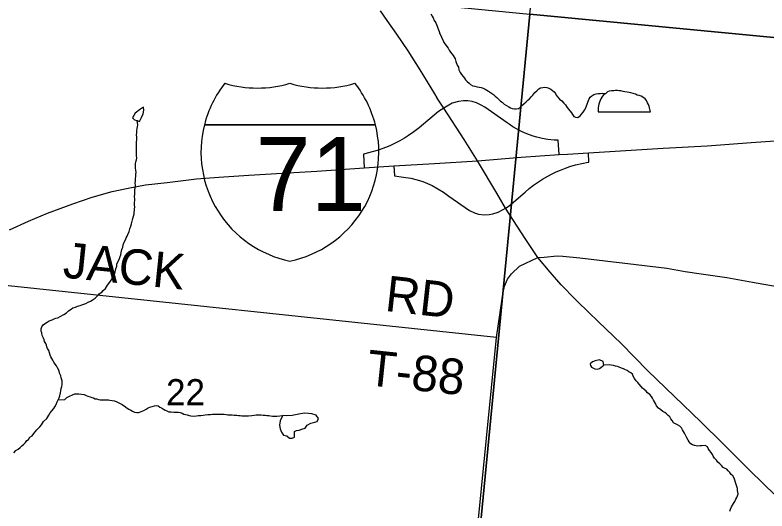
# Model space of a CAD drawing. Extents: x 1310247 to 1664935, y 284496 to 704931.
# Drawn here: x 1497662 to 1504004, y 515913 to 520097 of the extents above; entities that cross this region are included whole.
import ezdxf

# ---------------------------------------------------------------- set-up
doc = ezdxf.new("R2010")
doc.units = 0
for name, color, linetype in [('GM_X_Airport_Location_Class_3', 7, 'Continuous'), ('GM_X_County', 7, 'Continuous'), ('GM_X_County_Subdivision_Text', 7, 'Continuous'), ('GM_X_Interstate_Shield', 7, 'Continuous'), ('GM_X_Minor_River', 7, 'Continuous'), ('GM_X_Minor_River_Text', 7, 'Continuous'), ('GM_X_State_Shield', 7, 'Continuous'), ('GM_X_Township_Subdivision', 7, 'Continuous'), ('GM_X_US_Location', 7, 'Continuous'), ('GM_X_US_Route', 7, 'Continuous'), ('GM_X_US_Shield', 7, 'Continuous')]:
    doc.layers.add(name, color=color, linetype=linetype)

msp = doc.modelspace()

# ---------------------------------------------------------------- linework, layer by layer
at = {"layer": 'GM_X_County'}
for points in [[(1502528.3, 524873.1), (1507676.2, 524402.8), (1507180.6, 519609.2), (1502005.1, 520103.9)], [(1496845.7, 520606.4), (1502005.1, 520103.9), (1501457.6, 514459.3), (1496329.6, 514931.2)], [(1502005.1, 520103.9), (1507180.6, 519609.2), (1506637.6, 513990.6), (1501457.6, 514459.3)]]:
    msp.add_lwpolyline(points, close=True, dxfattribs=at)
at = {"layer": 'GM_X_County_Subdivision_Text'}
for points in [[(1501771.5, 517702.4), (1501779.6, 517756), (1501791.6, 517808.8), (1501816.5, 517868.7), (1501848.4, 517913.6), (1501916.8, 517977.7), (1502071.6, 518051)], [(1501722.1, 517377.3), (1497366.9, 517838.7), (1497333.5, 517849.9), (1497320.3, 517874.9), (1497324.8, 517900.7), (1497345.8, 517902.7), (1497363.7, 517887.9), (1497374.1, 517861.4), (1497366.9, 517839.7)], [(1501430.9, 514433.2), (1501430.9, 514433.2), (1501722.1, 517377.3), (1501771.5, 517702.4)]]:
    msp.add_lwpolyline(points, dxfattribs=at)
at = {"layer": 'GM_X_Interstate_Shield'}
for points in [[(1501222.1, 519397.5), (1501202.6, 519431.8), (1501077.9, 519634.3), (1500977.1, 519793.8), (1500882.9, 519935), (1500801.6, 520049.7), (1500744.8, 520131.6)], [(1502071.6, 518051), (1501963.7, 518212.3), (1501798.8, 518468), (1501724.8, 518592.9), (1501561.7, 518867.1), (1501451, 519047.2), (1501277.9, 519310.8), (1501223.5, 519394.9), (1501222.1, 519397.5)], [(1502071.6, 518051), (1502125.9, 518053.8), (1502234, 518064.2), (1502281.4, 518063.7), (1502425, 518049.8), (1502640.5, 518023.3), (1502901.8, 517991.4), (1503159.2, 517961.5), (1503314.2, 517933.9), (1503448.3, 517912.7), (1503664.5, 517881.6), (1503882.6, 517842.4), (1504090.6, 517805.5)], [(1502391.3, 517695.5), (1502389.8, 517697), (1502267.1, 517821.8), (1502174.6, 517927.5), (1502071.6, 518051)], [(1504087.5, 516035.1), (1504000.8, 516116.6), (1503830, 516283.1), (1503632, 516482.2), (1503445.9, 516664.2), (1503223.7, 516879.2), (1503000.5, 517096.1), (1502773.7, 517324.6), (1502583.1, 517507.6), (1502408.3, 517678.1), (1502391.3, 517695.5)]]:
    msp.add_lwpolyline(points, dxfattribs=at)
at = {"layer": 'GM_X_Minor_River'}
for points in [[(1503022.3, 519280.2), (1503013.4, 519312.6), (1503009.8, 519326.7), (1503004.2, 519340.9), (1502996.8, 519357.2), (1502987.3, 519375.5), (1502975.7, 519389.9), (1502958.1, 519402.5), (1502942.3, 519411), (1502926.4, 519417.5), (1502908.5, 519422), (1502894.6, 519428.5), (1502874.7, 519435.1), (1502856.8, 519439.6), (1502840.9, 519444.1), (1502824.9, 519446.6), (1502804.9, 519449.2), (1502790.9, 519451.7), (1502771, 519456.3), (1502757, 519458.7), (1502742.9, 519459.2), (1502726.9, 519459.7), (1502712.8, 519458.1), (1502692.7, 519458.7), (1502674.4, 519453.3), (1502660.2, 519447.7), (1502643.7, 519436.2), (1502625.2, 519422.7), (1502610.5, 519403.2), (1502604, 519389.3), (1502597.5, 519375.5), (1502591, 519361.7), (1502586.4, 519343.8), (1502583.9, 519329.8), (1502581.5, 519315.9), (1502580.9, 519297.9), (1502580.3, 519279.9)], [(1498653.6, 519229.4), (1498671.3, 519212.9), (1498693.2, 519206.3), (1498711.1, 519199.9), (1498728, 519231.6), (1498742.8, 519263.3), (1498749.6, 519293.3), (1498746.2, 519319.5), (1498711.5, 519296.2), (1498674.6, 519269)], [(1498674.6, 519269), (1498653.6, 519229.4)], [(1502580.3, 519279.9), (1503008.3, 519280.7), (1503022.3, 519280.2)], [(1499922.2, 516717.8), (1499907.5, 516692), (1499899.1, 516674.2), (1499894.1, 516636.2), (1499897.4, 516606), (1499910.8, 516577.5), (1499926.2, 516553.1), (1499954.2, 516546.4), (1499977.8, 516527.8), (1499999.9, 516527.2), (1500020.2, 516534.8), (1500018.9, 516562.9), (1500019.4, 516583), (1500035.7, 516592.6), (1500059.9, 516596), (1500080.2, 516603.6), (1500108.5, 516612.9), (1500127.2, 516636.5), (1500155.7, 516653.9), (1500192.1, 516663.1), (1500210.3, 516668.7), (1500221, 516694.5), (1500201.6, 516721.1), (1500165.7, 516732), (1500137.7, 516736.6), (1500099.6, 516739.6), (1500055.1, 516730.6)], [(1500055.1, 516730.6), (1500000.6, 516717.9), (1499954.3, 516717), (1499922.2, 516717.8)]]:
    msp.add_lwpolyline(points, dxfattribs=at)
at = {"layer": 'GM_X_Minor_River_Text'}
for points in [[(1501168.9, 520106.9), (1501180.3, 520086.5), (1501187.8, 520072.3), (1501197.1, 520049.9), (1501210.6, 520031.5), (1501216.2, 520017.3), (1501221.7, 520003.1), (1501229.2, 519986.8), (1501234.8, 519972.6), (1501238.3, 519958.5), (1501245.7, 519938.2), (1501255.1, 519917.9), (1501262.6, 519901.6), (1501274, 519881.3), (1501279.5, 519865.1), (1501291, 519850.7), (1501304.4, 519830.2), (1501314, 519815.9), (1501323.6, 519801.6), (1501335, 519783.2), (1501346.6, 519768.8), (1501356.2, 519754.5), (1501365.8, 519740.2), (1501373.3, 519725.9), (1501380.6, 519703.6), (1501391.7, 519673.2), (1501401.2, 519656.9), (1501406.5, 519634.7), (1501417.8, 519612.3), (1501427.2, 519594), (1501440.8, 519579.6), (1501454.4, 519565.1), (1501462, 519550.8), (1501475.6, 519536.4), (1501491.2, 519521.9), (1501504.9, 519511.5), (1501522.6, 519500.9), (1501540.6, 519496.3), (1501558.5, 519491.8), (1501576.5, 519489.2), (1501594.5, 519486.6), (1501610.4, 519480.1), (1501628.2, 519471.6), (1501641.9, 519463.1), (1501655.7, 519454.7), (1501681.3, 519437.9), (1501699, 519427.3), (1501710.6, 519412.9), (1501726.3, 519402.4), (1501739.9, 519386), (1501757.5, 519371.4), (1501771.2, 519361), (1501788.7, 519344.4), (1501808.5, 519333.8), (1501826.2, 519323.2), (1501842, 519314.7), (1501855.8, 519308.3), (1501873.8, 519305.7), (1501889.9, 519305.2), (1501908.1, 519308.6), (1501924.6, 519320.2), (1501937.1, 519333.8), (1501953.6, 519347.3)], [(1501953.6, 519347.3), (1501972.2, 519364.8), (1501986.8, 519378.3), (1502001.2, 519389.9), (1502015.9, 519407.5), (1502028.4, 519421.1), (1502047.2, 519442.6), (1502061.7, 519458.2), (1502080.3, 519473.6), (1502094.7, 519483.2), (1502112.9, 519486.7), (1502131, 519488.1), (1502147, 519485.6), (1502162.9, 519479.1), (1502180.7, 519470.5), (1502194.4, 519460.1), (1502208.1, 519449.7), (1502219.7, 519435.3), (1502227.3, 519421), (1502238.8, 519404.6), (1502254.3, 519386.1), (1502273.9, 519373.5), (1502291.3, 519352.9), (1502305, 519340.5), (1502314.5, 519324.1), (1502328, 519305.7), (1502345.4, 519285.1), (1502354.9, 519270.8), (1502362.5, 519256.5), (1502376.1, 519242.1), (1502389.9, 519235.7), (1502407.9, 519233.1), (1502428.5, 519246.5), (1502439, 519260.2), (1502453.6, 519277.8), (1502464.3, 519295.5), (1502475, 519315.2), (1502481.5, 519331), (1502488, 519344.8), (1502492.6, 519362.7), (1502499.1, 519376.5), (1502505.6, 519390.4), (1502512, 519404.2), (1502526.5, 519415.8), (1502544.9, 519425.2), (1502563.2, 519430.7), (1502581.4, 519434.1), (1502599.5, 519435.6), (1502615.6, 519437.1), (1502643.7, 519436.2)], [(1498672, 518547.1), (1498670.6, 518563.1), (1498671.4, 518587.1), (1498672, 518605.2), (1498672.6, 518623.2), (1498675, 518637.1), (1498677.8, 518661.1), (1498676.4, 518679.2), (1498679, 518697.1), (1498679.7, 518717.1), (1498680.3, 518735.1), (1498680.9, 518753.2), (1498683.4, 518769.1), (1498682, 518787.2), (1498678.6, 518805.3), (1498677.2, 518825.4), (1498679.7, 518841.4), (1498680.3, 518859.4), (1498686.9, 518875.2), (1498689.5, 518893.1), (1498688, 518909.2), (1498686.5, 518923.3), (1498687, 518939.3), (1498687.5, 518955.3), (1498688.1, 518971.3), (1498687, 518999.4), (1498687.8, 519023.4), (1498688.6, 519047.5), (1498689.2, 519067.5), (1498687.8, 519085.6), (1498688.4, 519103.6), (1498689, 519121.6), (1498691.6, 519139.5), (1498694.1, 519153.5), (1498696.7, 519171.4), (1498693.2, 519206.3)], [(1498040.5, 516885.5), (1498045.3, 516909.4), (1498047.8, 516925.4), (1498052.5, 516945.3), (1498057.1, 516963.2), (1498059.7, 516981.1), (1498060.2, 516995.1), (1498058.7, 517011.2), (1498051.6, 517037.5), (1498048.1, 517053.6), (1498038.8, 517075.9), (1498035.3, 517094.1), (1498020.1, 517120.6), (1498012.6, 517136.8), (1498001.1, 517151.2), (1497989.5, 517167.6), (1497982.1, 517185.9), (1497965, 517214.5), (1497959.4, 517228.6), (1497954, 517246.8), (1497946.6, 517267.1), (1497937.1, 517283.4), (1497931.5, 517297.6), (1497928, 517311.8), (1497922.4, 517326), (1497910.9, 517342.3), (1497907.4, 517356.5), (1497901.8, 517370.7), (1497892.5, 517393), (1497887.2, 517415.2), (1497881.6, 517429.4), (1497882.3, 517449.4), (1497888.9, 517467.2), (1497901.6, 517484.9), (1497934.4, 517505.9), (1497950.9, 517517.4), (1497975.3, 517526.7), (1497991.6, 517534.2), (1498005.9, 517539.8), (1498022, 517543.3), (1498042.5, 517554.7), (1498075.2, 517571.7), (1498095.8, 517585.1), (1498114.4, 517600.5), (1498135, 517615.9), (1498149.3, 517625.5), (1498173.7, 517632.8), (1498190, 517640.3), (1498210.3, 517647.7), (1498226.5, 517651.2), (1498242.9, 517658.7), (1498259.1, 517664.2), (1498279.5, 517673.6), (1498299.9, 517683), (1498314.3, 517692.5), (1498336.9, 517707.9), (1498359.8, 517731.2), (1498372.3, 517744.8), (1498394.9, 517760.2), (1498405.4, 517773.9), (1498424.1, 517791.3), (1498443, 517816.8), (1498461.9, 517842.3), (1498472.5, 517860), (1498483.2, 517879.7), (1498491.7, 517893.4), (1498502.4, 517911.1), (1498507, 517931), (1498513.9, 517956.9), (1498520.7, 517978.7), (1498521.2, 517994.7), (1498527.7, 518008.5), (1498536.4, 518028.3), (1498542.9, 518044.1), (1498549.5, 518060), (1498553.9, 518073.8), (1498558.6, 518093.7), (1498563.5, 518119.6), (1498572.2, 518139.4), (1498574.8, 518157.3), (1498583.6, 518181.1), (1498594.3, 518200.8), (1498600.9, 518216.6), (1498607.3, 518230.5), (1498613.8, 518244.3), (1498624.7, 518270), (1498631.5, 518293.8), (1498638.3, 518315.7), (1498645, 518335.5), (1498649.7, 518357.4), (1498656.5, 518381.2), (1498661.2, 518401.1), (1498665.8, 518419), (1498668.3, 518433), (1498670.7, 518446.9), (1498671.3, 518462.9), (1498671.7, 518476.9), (1498670.3, 518495), (1498671, 518515), (1498671.6, 518533), (1498672, 518547.1)], [(1502629.5, 517143.2), (1502622.2, 517175.5), (1502592.4, 517188.2), (1502556, 517179.1), (1502531.7, 517171.6), (1502513.2, 517154), (1502514.9, 517140), (1502524.6, 517125.7)], [(1503703, 516221.8), (1503691.5, 516238.1), (1503677.8, 516250.6), (1503664.2, 516265), (1503650.4, 516271.5), (1503634.6, 516280), (1503621, 516296.4), (1503605.4, 516310.9), (1503589.9, 516325.4), (1503578.3, 516341.8), (1503562.8, 516358.3), (1503551.4, 516376.7), (1503543.8, 516391), (1503532.3, 516407.4), (1503518.7, 516423.8), (1503509.3, 516440.1), (1503501.7, 516454.4), (1503483.9, 516465), (1503455.8, 516463.8), (1503437.6, 516462.4), (1503419.5, 516460.9), (1503405.5, 516461.4), (1503391.5, 516465.8), (1503375.7, 516472.3), (1503361.9, 516480.7), (1503348.3, 516495.2), (1503338.7, 516509.5), (1503327.4, 516529.9), (1503318, 516552.2), (1503308.6, 516570.5), (1503301, 516584.8), (1503291.5, 516599.1), (1503283.9, 516613.4), (1503268.4, 516629.9), (1503250.6, 516640.5), (1503232.8, 516649), (1503217, 516655.5), (1503203.6, 516676), (1503192, 516690.4), (1503184.5, 516706.6), (1503170.8, 516719.1), (1503157.3, 516733.5), (1503141.5, 516744), (1503125.7, 516752.5), (1503108.1, 516765.1), (1503088.5, 516781.7), (1503071.1, 516800.3), (1503063.6, 516818.5), (1503056.1, 516832.8), (1503046.5, 516847.1), (1503039, 516865.4), (1503031.5, 516879.6), (1503015.9, 516896.1), (1502996.3, 516910.8), (1502984.8, 516925.2), (1502969.1, 516937.7), (1502955.4, 516950.1), (1502943.9, 516964.5), (1502926.4, 516983.1), (1502914.8, 516997.5), (1502901.2, 517009.9), (1502887.8, 517030.3), (1502876.4, 517050.7), (1502868.9, 517067), (1502855.2, 517077.4), (1502839.4, 517087.9), (1502823.7, 517098.4), (1502809.9, 517104.9), (1502794, 517111.4), (1502776.1, 517117.9), (1502758.3, 517126.5), (1502744.4, 517130.9), (1502726.5, 517135.5), (1502708.5, 517140.1), (1502690.5, 517142.6), (1502676.6, 517145.1), (1502629.5, 517143.2)], [(1502524.6, 517125.7), (1502552.4, 517111), (1502572.4, 517108.5), (1502592.6, 517114), (1502629.5, 517143.2)], [(1498027.3, 516849.9), (1498081.7, 516854.2), (1498100.3, 516869.7), (1498120.7, 516881), (1498147.2, 516892.3), (1498165.6, 516901.7), (1498183.7, 516901.1), (1498199.8, 516902.7), (1498221.8, 516900), (1498245.8, 516895.2), (1498263.7, 516888.6), (1498277.5, 516882.2), (1498295.4, 516875.6), (1498309.3, 516871.2), (1498323.2, 516866.8), (1498337.1, 516860.3), (1498351, 516857.9), (1498367, 516853.4), (1498381, 516851), (1498395, 516850.5), (1498413.1, 516852), (1498433.2, 516851.4), (1498449.3, 516850.9), (1498463.3, 516848.4), (1498481.3, 516845.9), (1498501.2, 516841.2), (1498521.1, 516834.6), (1498544.8, 516821.9), (1498566.5, 516811.2), (1498594, 516792.3), (1498607.7, 516781.9), (1498621.5, 516771.4), (1498639.3, 516762.8), (1498653, 516754.4), (1498670.8, 516745.8), (1498690.9, 516743.2), (1498704.9, 516742.8), (1498719.2, 516748.4), (1498747.7, 516761.5), (1498768.2, 516772.9), (1498784.6, 516784.4), (1498798.8, 516788), (1498819.2, 516795.4), (1498837.4, 516800.8), (1498853.5, 516802.3), (1498869.5, 516799.8), (1498883.3, 516789.4), (1498897.1, 516782.9), (1498914.9, 516772.4), (1498928.6, 516763.9), (1498942.5, 516757.5), (1498960.4, 516750.9), (1498978.4, 516748.4), (1499000.4, 516747.7), (1499020.5, 516747.1), (1499040.6, 516746.5), (1499054.6, 516744), (1499072.4, 516737.5), (1499086.3, 516731), (1499114.2, 516724.1), (1499130, 516717.6), (1499146, 516715.1), (1499164, 516712.6), (1499192.3, 516715.7), (1499206.4, 516717.3), (1499230.5, 516718.5), (1499248.7, 516722), (1499264.9, 516723.5), (1499287.1, 516726.8), (1499311.2, 516728.1), (1499327.4, 516729.6), (1499355.5, 516730.7), (1499369.6, 516730.3), (1499385.6, 516729.8), (1499401.7, 516729.3), (1499425.8, 516728.5), (1499441.8, 516728), (1499457.8, 516725.5), (1499475.8, 516723), (1499494, 516724.4), (1499510, 516721.9), (1499532, 516721.3), (1499546, 516718.8), (1499560.1, 516718.4), (1499574.1, 516715.9), (1499592.1, 516715.4), (1499612.2, 516714.8), (1499632.3, 516716.1), (1499658.6, 516719.3), (1499678.8, 516722.7), (1499694.9, 516724.2), (1499708.9, 516723.8), (1499723, 516723.4), (1499739.1, 516722.9), (1499755.1, 516722.4), (1499771.2, 516721.9)], [(1497652.9, 516404.6), (1497669.6, 516422.1), (1497688.1, 516435.6), (1497706.6, 516449), (1497721.1, 516462.6), (1497735.7, 516478.2), (1497750.2, 516489.8), (1497760.8, 516507.5), (1497775.2, 516517.1), (1497787.8, 516534.7), (1497806.3, 516546.1), (1497821, 516567.7), (1497831.5, 516581.4), (1497846.1, 516597), (1497860.6, 516610.6), (1497871.1, 516624.3), (1497885.7, 516639.9), (1497902.8, 516669.4), (1497929.6, 516692.6), (1497938.1, 516706.4), (1497946.6, 516720.1), (1497957.3, 516739.8), (1497972, 516757.4), (1497988.7, 516776.9), (1497999.2, 516790.6), (1498009.9, 516810.3), (1498018.7, 516834.1), (1498027.3, 516849.9), (1498033.9, 516867.7), (1498040.5, 516885.5)], [(1499771.2, 516721.9), (1499785.2, 516719.5), (1499803.2, 516718.9), (1499817.2, 516716.5), (1499833.2, 516714), (1499853.3, 516713.3), (1499871.3, 516712.8), (1499922.2, 516717.8)], [(1503690.7, 515911.6), (1503697.3, 515927.4), (1503703.9, 515947.2), (1503712.5, 515963), (1503721, 515976.8), (1503731.6, 515994.5), (1503740.2, 516012.2), (1503750.7, 516026), (1503755.2, 516039.8), (1503759.8, 516057.7), (1503756.7, 516085.9), (1503755.3, 516102), (1503749.8, 516120.1), (1503744.3, 516136.3), (1503738.9, 516154.5), (1503733.5, 516172.7), (1503726.1, 516191), (1503716.6, 516209.3), (1503703, 516221.8)]]:
    msp.add_lwpolyline(points, dxfattribs=at)
at = {"layer": 'GM_X_State_Shield'}
msp.add_lwpolyline([(1497615.7, 518285.1), (1497776.1, 518357.6), (1497936.4, 518426.1), (1498151.1, 518503.3), (1498313.1, 518559.8), (1498481, 518608), (1498616.2, 518634.9), (1498763.5, 518663.6), (1498946.8, 518685.4), (1499192.5, 518713.8), (1499381.7, 518729.4), (1499635.2, 518745.6), (1499914.8, 518763.2), (1500208.4, 518778.4), (1500607.8, 518809.2), (1500857.3, 518825.4), (1501200.3, 518845.6), (1501561.7, 518867.1), (1501930.7, 518896.8), (1502251.3, 518919.3), (1502323, 518923.8), (1502497.7, 518934.7), (1503129.6, 518973.2), (1503499.7, 518994.7), (1503870, 519022.2), (1504236.1, 519045.8)], dxfattribs=at)
at = {"layer": 'GM_X_US_Route'}
for points in [[(1502251.3, 518919.3), (1502242.8, 519040.7), (1502209.4, 519042.3), (1502156.2, 519047.6), (1502107.7, 519055.8), (1502063.3, 519066.3), (1502031, 519075.8), (1501979.1, 519094.4), (1501940.6, 519111.2), (1501898.3, 519132.6), (1501860.5, 519154.9), (1501829.3, 519175.6), (1501813, 519187.3), (1501624.4, 519318.5), (1501593.8, 519337.5), (1501555.5, 519354.8), (1501517.2, 519366.3), (1501481.2, 519372.3), (1501445.3, 519373.9), (1501402.2, 519368.5), (1501350.3, 519353.4), (1501320.2, 519337.8), (1501277.9, 519310.8)], [(1501277.9, 519310.8), (1501233, 519282.2), (1501069.4, 519146.3), (1501024.8, 519111), (1500980.1, 519079.6), (1500946.7, 519058.2), (1500906.6, 519035), (1500862.5, 519012.2), (1500829, 518996.5), (1500795.6, 518982.4), (1500756, 518967.4), (1500727.3, 518957.8), (1500675.2, 518942.5), (1500612.6, 518925.2), (1500600.2, 518923.6), (1500607.8, 518809.2)], [(1501798.8, 518468), (1501828.8, 518486.8), (1501964.9, 518603.9), (1501999.3, 518633.1), (1502034.2, 518660.3), (1502068.8, 518685.1), (1502111.2, 518712.6), (1502154.8, 518738), (1502191, 518757), (1502227.2, 518774.3), (1502262.3, 518789.3), (1502303.8, 518805.4), (1502342.7, 518818.5), (1502388.6, 518831.9), (1502443.2, 518845), (1502495.8, 518855.8), (1502502.6, 518856.8), (1502497.7, 518934.7)], [(1500857.3, 518825.4), (1500863, 518740.6), (1500939.6, 518729.9), (1501001.8, 518720), (1501053.2, 518707.3), (1501100.7, 518691.8), (1501181.1, 518657.7), (1501228.8, 518631), (1501274.7, 518601.6), (1501319.9, 518568.6), (1501494.5, 518448.9), (1501536.4, 518427.6), (1501570.7, 518417), (1501619, 518410.8), (1501660, 518413), (1501691.5, 518419.5), (1501737.9, 518433.4), (1501778.1, 518455.1), (1501798.8, 518468)]]:
    msp.add_lwpolyline(points, dxfattribs=at)
at = {"layer": 'GM_X_US_Shield'}
for p, q in [((1499259.2, 519170), (1500702, 519170)), ((1500702, 519170), (1499259.2, 519170)), ((1500702, 519170), (1499259.2, 519170))]:
    msp.add_line(p, q, dxfattribs=at)
for centre, start, end in [((1500168.1, 518940.1), 141.66896, 165.80665), ((1499706.7, 520418.1), 253.00908, 286.99093), ((1500254.6, 520418.1), 253.00908, 286.99093), ((1499793.1, 518940.1), 14.19335, 38.33104), ((1500168.1, 518940.1), 165.80665, 258.46304), ((1499793.1, 518940.1), 281.53696, 14.19335)]:
    msp.add_arc(centre, 937.5, start, end, dxfattribs=at)

# ---------------------------------------------------------------- texts
at = {"layer": 'GM_X_Airport_Location_Class_3'}
for s in ['-', '.', ',']:
    msp.add_text(s, height=1, dxfattribs=at).set_placement((1499980.4, 518771))
msp.add_text('71', height=1, rotation=0.00001, dxfattribs=at).set_placement((1499776.2, 518564))
at = {"layer": 'GM_X_Township_Subdivision'}
for s, rotation, p in [('JACK', 354.20725, (1498058.9, 517883.6)), ('RD', 353.60543, (1500774.9, 517601.8)), ('T-88', 353.97305, (1500619.1, 516975.5))]:
    msp.add_text(s, height=300, rotation=rotation, dxfattribs=at).set_placement(p)
at = {"layer": 'GM_X_US_Location'}
msp.add_text('22', height=221, rotation=0.00001, dxfattribs=at).set_placement((1498935.8, 516804.5))
at = {"layer": 'GM_X_US_Shield'}
msp.add_text('71', height=625, dxfattribs=at).set_placement((1499691.9, 518443.4))

doc.saveas('drawing.dxf')
